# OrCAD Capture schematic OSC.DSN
size A; company: OrCAD; note: OSC
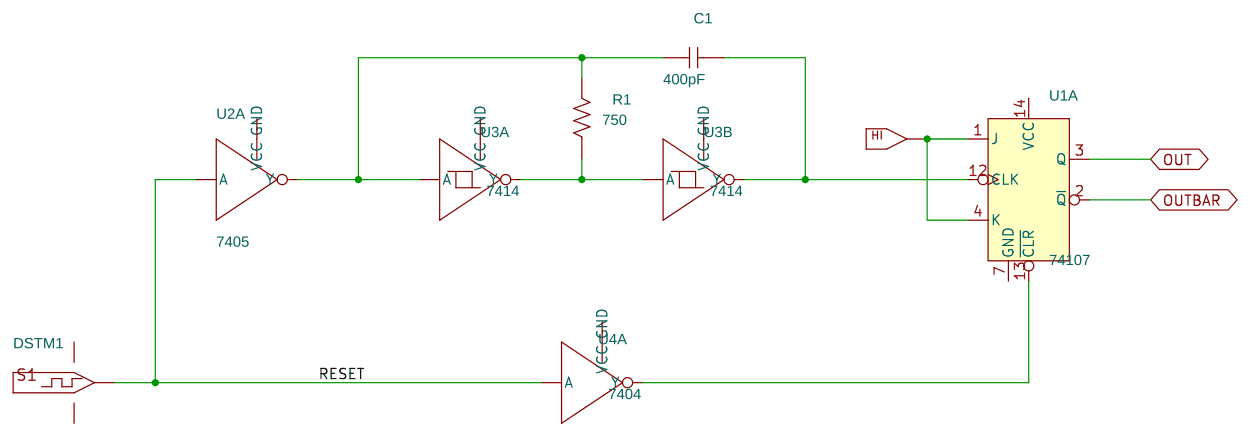
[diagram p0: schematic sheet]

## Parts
C1  400pF  [CK05]
DSTM1  DigStim1
R1  750  [RC05]
U1  74107  [DIP.100/14/W.300/L.800]  (section A)
U2  7405  [DIP.100/14/W.300/L.800]  (section A)
U3  7414  [DIP.100/14/W.300/L.800]  (sections A,B)
U4  7404  [DIP.100/14/W.300/L.800]  (section A)

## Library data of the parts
C1 = C
DSTM1 = DigStim1
R1 = R
U1 = 74107
U2 = 7405
U3 = 7414
U4 = 7404

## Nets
GND: DSTM1.3(GND) U1.7(GND) U2.7(GND) U3.7(GND) U4.7(GND)
VCC: DSTM1.2(VCC) U1.14(VCC) U2.14(VCC) U3.14(VCC) U4.14(VCC)
$D_HI: U1.1(J) U1.4(K)
OUT: U1.3(Q)
OUTBAR: U1.2(~{Q})
RESET: DSTM1.OUT U2.1(A) U4.1(A)
N00041: U1.13(~{CLR}) U4.2(Y)
N00050: R1.1 U3.2(Y) U3.3(A)
N00075: C1.2 U1.12(CLK) U3.4(Y)
N00112: C1.1 R1.2 U2.2(Y) U3.1(A)
